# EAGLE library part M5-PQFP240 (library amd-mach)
AMD MACH SERIES
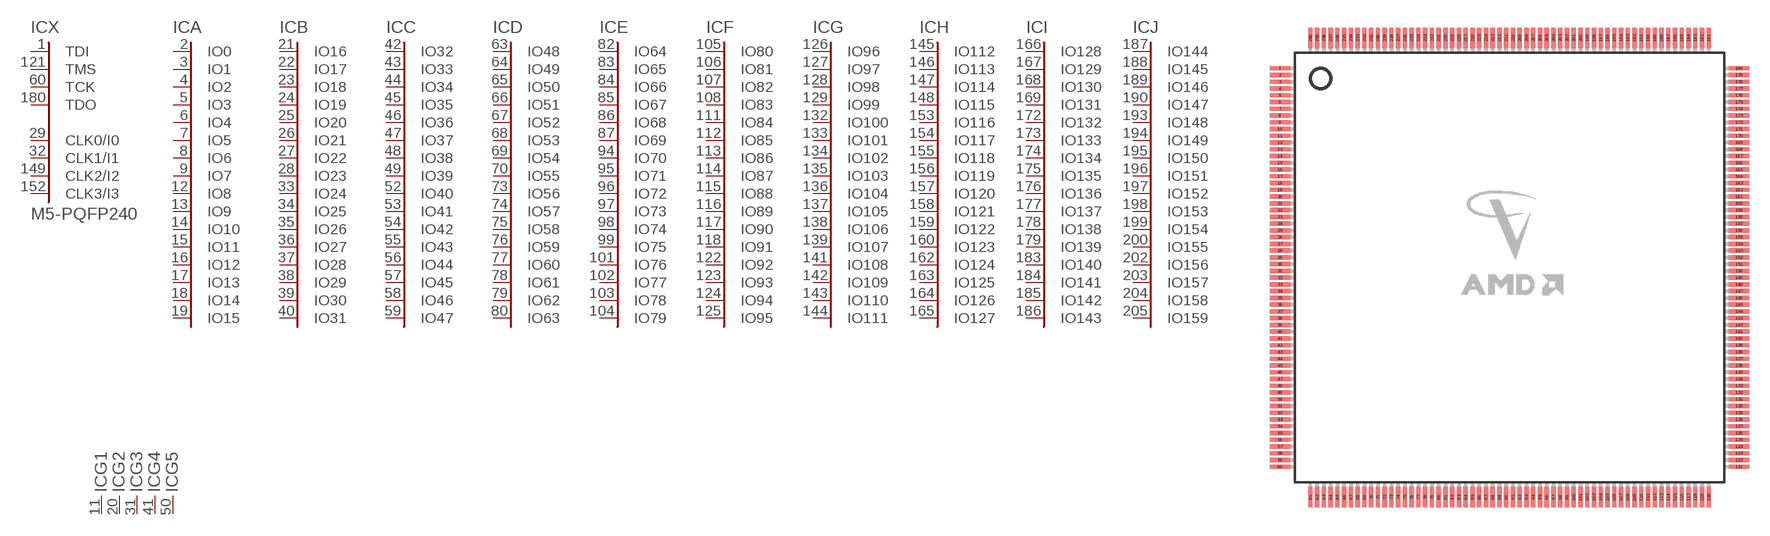
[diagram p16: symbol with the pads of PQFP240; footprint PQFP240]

Designator prefix IC; gates X=M5-CTRL A=IO15 B=IO31 C=IO47 D=IO63 E=IO79 F=IO95 G=IO111 H=IO127 I=IO143 J=IO159 G1=GND G2=GND G3=GND G4=GND G5=GND G6=GND G7=GND G8=GND G9=GND G10=GND G11=GND G12=GND G13=GND G14=GND G15=GND G16=GND G17=GND G18=GND G19=GND G20=GND G21=GND G22=GND G23=GND G24=GND G25=GND G26=GND V1=VCC V2=VCC V3=VCC V4=VCC V5=VCC V6=VCC V7=VCC V8=VCC V9=VCC V10=VCC V11=VCC V12=VCC V13=VCC V14=VCC V15=VCC V16=VCC V17=VCC V18=VCC G27=GND G28=GND G29=GND G30=GND K=IO175 L=IO183

## M5-PQFP240 (OC_FARNELL: unknown; OC_NEWARK: unknown)  [PQFP240]
1  X:TDI  in
2  A:IO0
3  A:IO1
4  A:IO2
5  A:IO3
6  A:IO4
7  A:IO5
8  A:IO6
9  A:IO7
10  V1:VCC  pwr
11  G1:GND  pwr
12  A:IO8
13  A:IO9
14  A:IO10
15  A:IO11
16  A:IO12
17  A:IO13
18  A:IO14
19  A:IO15
20  G2:GND  pwr
21  B:IO16
22  B:IO17
23  B:IO18
24  B:IO19
25  B:IO20
26  B:IO21
27  B:IO22
28  B:IO23
29  X:CLK0/I0  in
30  V2:VCC  pwr
31  G3:GND  pwr
32  X:CLK1/I1  in
33  B:IO24
34  B:IO25
35  B:IO26
36  B:IO27
37  B:IO28
38  B:IO29
39  B:IO30
40  B:IO31
41  G4:GND  pwr
42  C:IO32
43  C:IO33
44  C:IO34
45  C:IO35
46  C:IO36
47  C:IO37
48  C:IO38
49  C:IO39
50  G5:GND  pwr
51  V3:VCC  pwr
52  C:IO40
53  C:IO41
54  C:IO42
55  C:IO43
56  C:IO44
57  C:IO45
58  C:IO46
59  C:IO47
60  X:TCK  in
61  G6:GND  pwr
62  V4:VCC  pwr
63  D:IO48
64  D:IO49
65  D:IO50
66  D:IO51
67  D:IO52
68  D:IO53
69  D:IO54
70  D:IO55
71  G7:GND  pwr
72  V5:VCC  pwr
73  D:IO56
74  D:IO57
75  D:IO58
76  D:IO59
77  D:IO60
78  D:IO61
79  D:IO62
80  D:IO63
81  G8:GND  pwr
82  E:IO64
83  E:IO65
84  E:IO66
85  E:IO67
86  E:IO68
87  E:IO69
88  V6:VCC  pwr
89  G9:GND  pwr
90  G10:GND  pwr
91  G11:GND  pwr
92  G12:GND  pwr
93  V7:VCC  pwr
94  E:IO70
95  E:IO71
96  E:IO72
97  E:IO73
98  E:IO74
99  E:IO75
100  G13:GND  pwr
101  E:IO76
102  E:IO77
103  E:IO78
104  E:IO79
105  F:IO80
106  F:IO81
107  F:IO82
108  F:IO83
109  V8:VCC  pwr
110  G14:GND  pwr
111  F:IO84
112  F:IO85
113  F:IO86
114  F:IO87
115  F:IO88
116  F:IO89
117  F:IO90
118  F:IO91
119  V9:VCC  pwr
120  G15:GND  pwr
121  X:TMS  in
122  F:IO92
123  F:IO93
124  F:IO94
125  F:IO95
126  G:IO96
127  G:IO97
128  G:IO98
129  G:IO99
130  V10:VCC  pwr
131  G16:GND  pwr
132  G:IO100
133  G:IO101
134  G:IO102
135  G:IO103
136  G:IO104
137  G:IO105
138  G:IO106
139  G:IO107
140  G17:GND  pwr
141  G:IO108
142  G:IO109
143  G:IO110
144  G:IO111
145  H:IO112
146  H:IO113
147  H:IO114
148  H:IO115
149  X:CLK2/I2  in
150  V11:VCC  pwr
151  G18:GND  pwr
152  X:CLK3/I3  in
153  H:IO116
154  H:IO117
155  H:IO118
156  H:IO119
157  H:IO120
158  H:IO121
159  H:IO122
160  H:IO123
161  G19:GND  pwr
162  H:IO124
163  H:IO125
164  H:IO126
165  H:IO127
166  I:IO128
167  I:IO129
168  I:IO130
169  I:IO131
170  G20:GND  pwr
171  V12:VCC  pwr
172  I:IO132
173  I:IO133
174  I:IO134
175  I:IO135
176  I:IO136
177  I:IO137
178  I:IO138
179  I:IO139
180  X:TDO  in
181  G21:GND  pwr
182  V13:VCC  pwr
183  I:IO140
184  I:IO141
185  I:IO142
186  I:IO143
187  J:IO144
188  J:IO145
189  J:IO146
190  J:IO147
191  G22:GND  pwr
192  V14:VCC  pwr
193  J:IO148
194  J:IO149
195  J:IO150
196  J:IO151
197  J:IO152
198  J:IO153
199  J:IO154
200  J:IO155
201  G23:GND  pwr
202  J:IO156
203  J:IO157
204  J:IO158
205  J:IO159
206  K:IO160
207  K:IO161
208  V15:VCC  pwr
209  G24:GND  pwr
210  G25:GND  pwr
211  G26:GND  pwr
212  G27:GND  pwr
213  V16:VCC  pwr
214  K:IO162
215  K:IO163
216  K:IO164
217  K:IO165
218  K:IO166
219  K:IO167
220  G28:GND  pwr
221  K:IO168
222  K:IO169
223  K:IO170
224  K:IO171
225  K:IO172
226  K:IO173
227  K:IO174
228  K:IO175
229  V17:VCC  pwr
230  G29:GND  pwr
231  L:IO176
232  L:IO177
233  L:IO178
234  L:IO179
235  L:IO180
236  L:IO181
237  L:IO182
238  L:IO183
239  V18:VCC  pwr
240  G30:GND  pwr

## Footprint PQFP240 (pad centres in mm)
PLASTIC QUAD FLAT PACK
smd 1.5 x 0.32: 1 -17,14.75; 2 -17,14.25; 3 -17,13.75; 4 -17,13.25; 5 -17,12.75; 6 -17,12.25; 7 -17,11.75; 8 -17,11.25; 9 -17,10.75; 10 -17,10.25; 11 -17,9.75; 12 -17,9.25; 13 -17,8.75; 14 -17,8.25; 15 -17,7.75; 16 -17,7.25; 17 -17,6.75; 18 -17,6.25; 19 -17,5.75; 20 -17,5.25; 21 -17,4.75; 22 -17,4.25; 23 -17,3.75; 24 -17,3.25; 25 -17,2.75; 26 -17,2.25; 27 -17,1.75; 28 -17,1.25; 29 -17,0.75; 30 -17,0.25; 31 -17,-0.25; 32 -17,-0.75; 33 -17,-1.25; 34 -17,-1.75; 35 -17,-2.25; 36 -17,-2.75; 37 -17,-3.25; 38 -17,-3.75; 39 -17,-4.25; 40 -17,-4.75; 41 -17,-5.25; 42 -17,-5.75; 43 -17,-6.25; 44 -17,-6.75; 45 -17,-7.25; 46 -17,-7.75; 47 -17,-8.25; 48 -17,-8.75; 49 -17,-9.25; 50 -17,-9.75; 51 -17,-10.25; 52 -17,-10.75; 53 -17,-11.25; 54 -17,-11.75; 55 -17,-12.25; 56 -17,-12.75; 57 -17,-13.25; 58 -17,-13.75; 59 -17,-14.25; 60 -17,-14.75; 121 17,-14.75; 122 17,-14.25; 123 17,-13.75; 124 17,-13.25; 125 17,-12.75; 126 17,-12.25; 127 17,-11.75; 128 17,-11.25; 129 17,-10.75; 130 17,-10.25; 131 17,-9.75; 132 17,-9.25; 133 17,-8.75; 134 17,-8.25; 135 17,-7.75; 136 17,-7.25; 137 17,-6.75; 138 17,-6.25; 139 17,-5.75; 140 17,-5.25; 141 17,-4.75; 142 17,-4.25; 143 17,-3.75; 144 17,-3.25; 145 17,-2.75; 146 17,-2.25; 147 17,-1.75; 148 17,-1.25; 149 17,-0.75; 150 17,-0.25; 151 17,0.25; 152 17,0.75; 153 17,1.25; 154 17,1.75; 155 17,2.25; 156 17,2.75; 157 17,3.25; 158 17,3.75; 159 17,4.25; 160 17,4.75; 161 17,5.25; 162 17,5.75; 163 17,6.25; 164 17,6.75; 165 17,7.25; 166 17,7.75; 167 17,8.25; 168 17,8.75; 169 17,9.25; 170 17,9.75; 171 17,10.25; 172 17,10.75; 173 17,11.25; 174 17,11.75; 175 17,12.25; 176 17,12.75; 177 17,13.25; 178 17,13.75; 179 17,14.25; 180 17,14.75
smd 0.32 x 1.5: 61 -14.75,-17; 62 -14.25,-17; 63 -13.75,-17; 64 -13.25,-17; 65 -12.75,-17; 66 -12.25,-17; 67 -11.75,-17; 68 -11.25,-17; 69 -10.75,-17; 70 -10.25,-17; 71 -9.75,-17; 72 -9.25,-17; 73 -8.75,-17; 74 -8.25,-17; 75 -7.75,-17; 76 -7.25,-17; 77 -6.75,-17; 78 -6.25,-17; 79 -5.75,-17; 80 -5.25,-17; 81 -4.75,-17; 82 -4.25,-17; 83 -3.75,-17; 84 -3.25,-17; 85 -2.75,-17; 86 -2.25,-17; 87 -1.75,-17; 88 -1.25,-17; 89 -0.75,-17; 90 -0.25,-17; 91 0.25,-17; 92 0.75,-17; 93 1.25,-17; 94 1.75,-17; 95 2.25,-17; 96 2.75,-17; 97 3.25,-17; 98 3.75,-17; 99 4.25,-17; 100 4.75,-17; 101 5.25,-17; 102 5.75,-17; 103 6.25,-17; 104 6.75,-17; 105 7.25,-17; 106 7.75,-17; 107 8.25,-17; 108 8.75,-17; 109 9.25,-17; 110 9.75,-17; 111 10.25,-17; 112 10.75,-17; 113 11.25,-17; 114 11.75,-17; 115 12.25,-17; 116 12.75,-17; 117 13.25,-17; 118 13.75,-17; 119 14.25,-17; 120 14.75,-17; 181 14.75,17; 182 14.25,17; 183 13.75,17; 184 13.25,17; 185 12.75,17; 186 12.25,17; 187 11.75,17; 188 11.25,17; 189 10.75,17; 190 10.25,17; 191 9.75,17; 192 9.25,17; 193 8.75,17; 194 8.25,17; 195 7.75,17; 196 7.25,17; 197 6.75,17; 198 6.25,17; 199 5.75,17; 200 5.25,17; 201 4.75,17; 202 4.25,17; 203 3.75,17; 204 3.25,17; 205 2.75,17; 206 2.25,17; 207 1.75,17; 208 1.25,17; 209 0.75,17; 210 0.25,17; 211 -0.25,17; 212 -0.75,17; 213 -1.25,17; 214 -1.75,17; 215 -2.25,17; 216 -2.75,17; 217 -3.25,17; 218 -3.75,17; 219 -4.25,17; 220 -4.75,17; 221 -5.25,17; 222 -5.75,17; 223 -6.25,17; 224 -6.75,17; 225 -7.25,17; 226 -7.75,17; 227 -8.25,17; 228 -8.75,17; 229 -9.25,17; 230 -9.75,17; 231 -10.25,17; 232 -10.75,17; 233 -11.25,17; 234 -11.75,17; 235 -12.25,17; 236 -12.75,17; 237 -13.25,17; 238 -13.75,17; 239 -14.25,17; 240 -14.75,17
